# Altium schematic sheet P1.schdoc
size 297 x 209 mm; Symbol: Drawing-Symbol_A4; Company: 嘉立创EDA; Version: V1.0; Page Size: A4; @Project Name: STM32-glove; @Page Count: 1; @Update Date: 2025-11-29; @Create Date: 2025-11-28; @Schematic Name: Schematic1; @Page No: 1; @Page Name: P1; @Board Name: Board1; @Create Time: 15:31:41; @Update Time: 04:53:44; Border: 1; Title Block Position: 3; Size: A4; Width: 1170; Height: 825; Region Start: 1; X Region Count: 6; Y Region Count: 4; Blade Width: 10; Device: Drawing-Symbol_A4
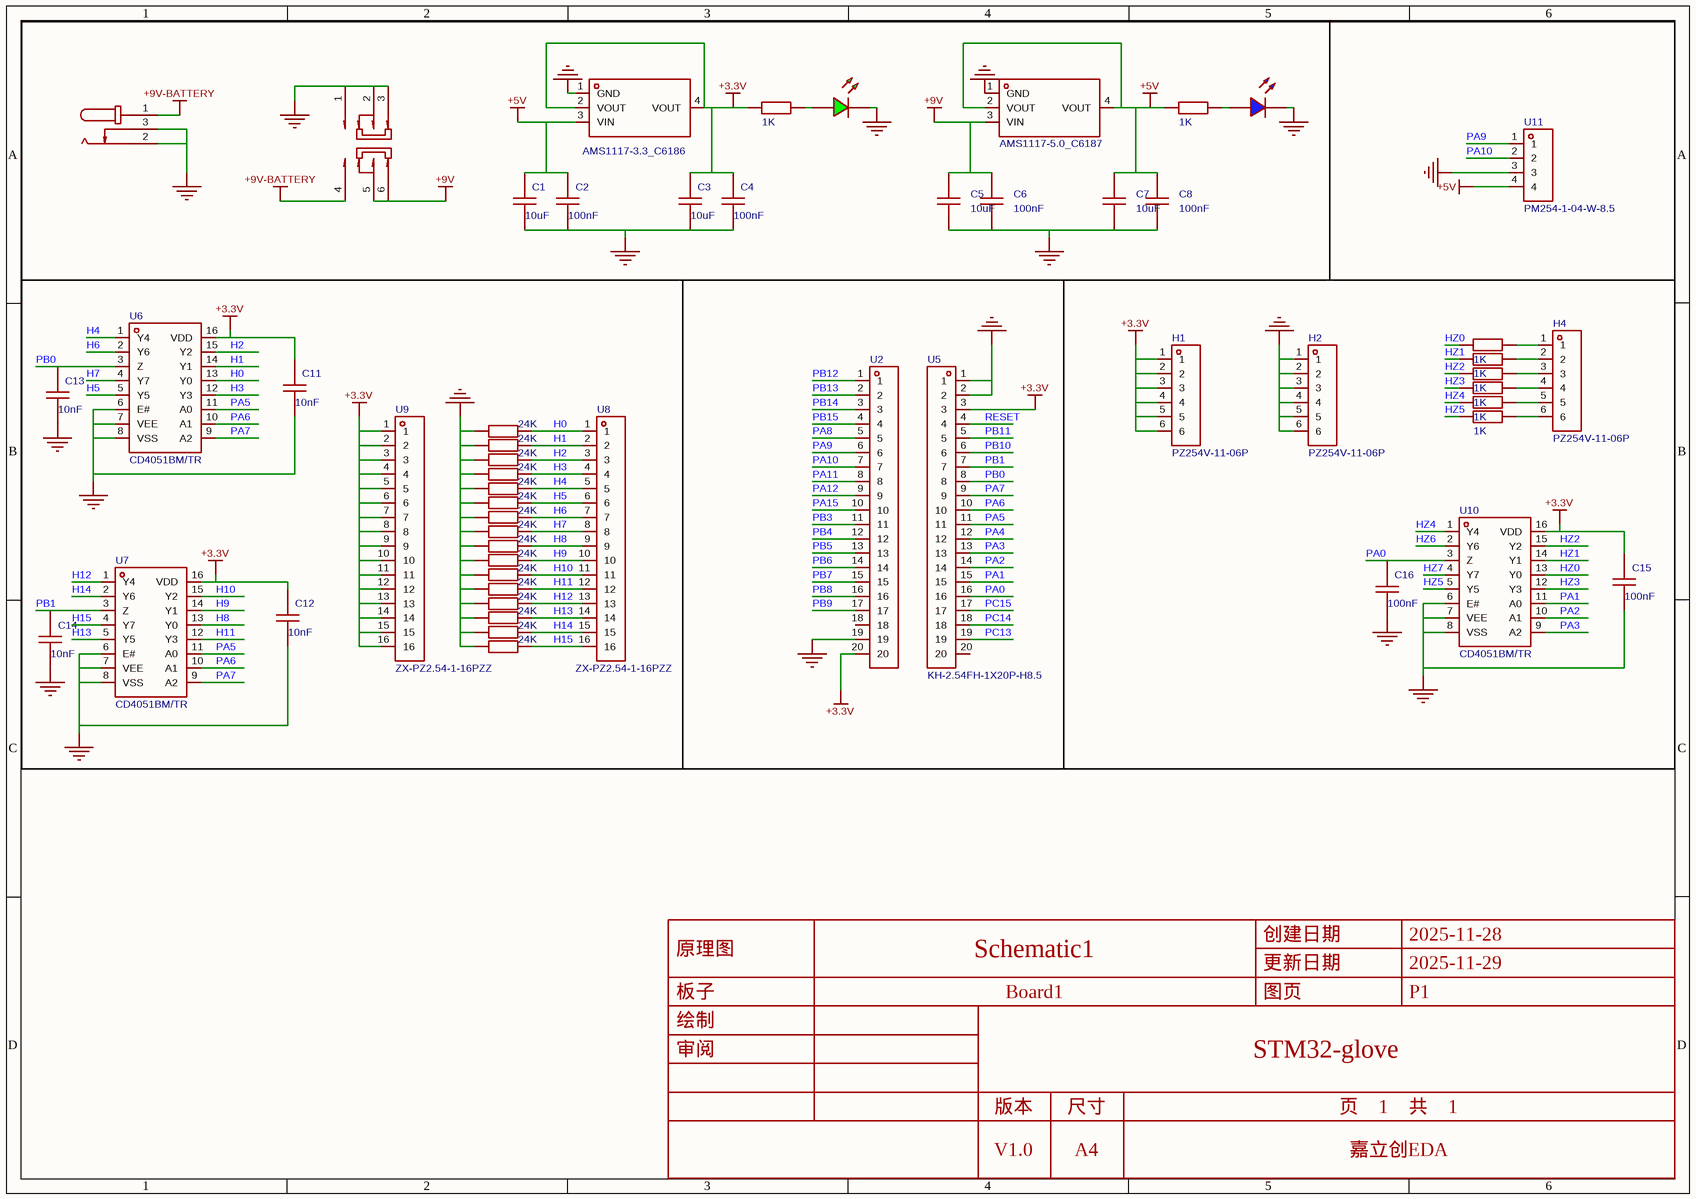
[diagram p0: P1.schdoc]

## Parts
C1  10uF  [C0805]
C2  100nF  [C0805]
C3  10uF  [C0805]
C4  100nF  [C0805]
C5  10uF  [C0805]
C6  100nF  [C0805]
C7  10uF  [C0805]
C8  100nF  [C0805]
C11  10nF  [C0805]
C12  10nF  [C0805]
C13  10nF  [C0805]
C14  10nF  [C0805]
C15  100nF  [C0805]
C16  100nF  [C0805]
DC1  DC-005-5A-2.0  [DC-IN-TH_DC-005-5A-2.0]  (value not drawn)
H1  PZ254V-11-06P  [HDR-TH_6P-P2.54-V-M]
H2  PZ254V-11-06P  [HDR-TH_6P-P2.54-V-M]
H4  PZ254V-11-06P  [HDR-TH_6P-P2.54-V-M]
LED1  LED_0805-G  [LED_0805]  (value not drawn)
LED2  LED_0805-B  [LED_0805]  (value not drawn)
R1  1K  [R0603]
R2  1K  [R0603]
R3  24K  [R0603]
R4  24K  [R0603]
R5  24K  [R0603]
R6  24K  [R0603]
R7  24K  [R0603]
R8  24K  [R0603]
R9  24K  [R0603]
R10  24K  [R0603]
R11  24K  [R0603]
R12  24K  [R0603]
R13  24K  [R0603]
R14  24K  [R0603]
R15  24K  [R0603]
R16  24K  [R0603]
R17  24K  [R0603]
R18  24K  [R0603]
R19  1K  [R0603]
R20  1K  [R0603]
R21  1K  [R0603]
R22  1K  [R0603]
R23  1K  [R0603]
R24  1K  [R0603]
SW1  SS-3235S-L1  [SW-SMD_SS-3235S-LX]  (value not drawn)
U2  KH-2.54FH-1X20P-H8.5  [HDR-TH_20P-P2.54-V-F-2]  (value not drawn)
U3  AMS1117-3.3_C6186  [SOT-223-3_L6.5-W3.4-P2.30-LS7.0-BR]
U4  AMS1117-5.0_C6187  [SOT-223_L6.5-W3.5-P2.30-LS7.0-BR]
U5  KH-2.54FH-1X20P-H8.5  [HDR-TH_20P-P2.54-V-F-2]
U6  CD4051BM/TR  [SOP-16_L9.9-W3.9-P1.27-LS6.1-BL]
U7  CD4051BM/TR  [SOP-16_L9.9-W3.9-P1.27-LS6.1-BL]
U8  ZX-PZ2.54-1-16PZZ  [HDR-TH_16P-P2.54-V-M-2]
U9  ZX-PZ2.54-1-16PZZ  [HDR-TH_16P-P2.54-V-M-2]
U10  CD4051BM/TR  [SOP-16_L9.9-W3.9-P1.27-LS6.1-BL]
U11  PM254-1-04-W-8.5  [HDR-TH_4P-P2.54-H-F-W10.0-N]

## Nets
+3.3V: C3.2 C4.2 C11.2 C12.2 C15.2 H1.1 H1.2 H1.3 H1.4 H1.5 H1.6 R1.1 U2.20 U3.2(VOUT) U3.4(VOUT) U5.3 U6.16(VDD) U7.16(VDD) U9.1 U9.2 U9.3 U9.4 U9.5 U9.6 U9.7 U9.8 U9.9 U9.10 U9.11 U9.12 U9.13 U9.14 U9.15 U9.16 U10.16(VDD)
+5V: C1.2 C2.2 C7.2 C8.2 R2.1 U3.3(VIN) U4.2(VOUT) U4.4(VOUT) U11.4
+9V: C5.2 C6.2 SW1.5 SW1.6 U4.3(VIN)
+9V-BATTERY: DC1.1 SW1.4
GND: C1.1 C2.1 C3.1 C4.1 C5.1 C6.1 C7.1 C8.1 C11.1 C12.1 C13.1 C14.1 C15.1 C16.1 DC1.2 DC1.3 H2.1 H2.2 H2.3 H2.4 H2.5 H2.6 LED1.1(C) LED2.1(C) R3.1 R4.1 R5.1 R6.1 R7.1 R8.1 R9.1 R10.1 R11.1 R12.1 R13.1 R14.1 R15.1 R16.1 R17.1 R18.1 SW1.1 SW1.2 SW1.3 U2.19 U3.1(GND) U4.1(GND) U5.1 U5.2 U6.6(E#) U6.7(VEE) U6.8(VSS) U7.6(E#) U7.7(VEE) U7.8(VSS) U10.6(E#) U10.7(VEE) U10.8(VSS) U11.3
H0: R3.2 U6.13(Y0) U8.1
H1: R4.2 U6.14(Y1) U8.2
H2: R5.2 U6.15(Y2) U8.3
H3: R6.2 U6.12(Y3) U8.4
H4: R7.2 U6.1(Y4) U8.5
H5: R8.2 U6.5(Y5) U8.6
H6: R9.2 U6.2(Y6) U8.7
H7: R10.2 U6.4(Y7) U8.8
H8: R11.2 U7.13(Y0) U8.9
H9: R12.2 U7.14(Y1) U8.10
H10: R13.2 U7.15(Y2) U8.11
H11: R14.2 U7.12(Y3) U8.12
H12: R15.2 U7.1(Y4) U8.13
H13: R16.2 U7.5(Y5) U8.14
H14: R17.2 U7.2(Y6) U8.15
H15: R18.2 U7.4(Y7) U8.16
HZ0: R19.1 U10.13(Y0)
HZ1: R20.1 U10.14(Y1)
HZ2: R21.1 U10.15(Y2)
HZ3: R22.1 U10.12(Y3)
HZ4: R23.1 U10.1(Y4)
HZ5: R24.1 U10.5(Y5)
HZ6: U10.2(Y6)
HZ7: U10.4(Y7)
PA0: C16.2 U5.16 U10.3(Z)
PA1: U5.15 U10.11(A0)
PA2: U5.14 U10.10(A1)
PA3: U5.13 U10.9(A2)
PA4: U5.12
PA5: U5.11 U6.11(A0) U7.11(A0)
PA6: U5.10 U6.10(A1) U7.10(A1)
PA7: U5.9 U6.9(A2) U7.9(A2)
PA8: U2.5
PA9: U2.6 U11.1
PA10: U2.7 U11.2
PA11: U2.8
PA12: U2.9
PA15: U2.10
PB0: C13.2 U5.8 U6.3(Z)
PB1: C14.2 U5.7 U7.3(Z)
PB3: U2.11
PB4: U2.12
PB5: U2.13
PB6: U2.14
PB7: U2.15
PB8: U2.16
PB9: U2.17
PB10: U5.6
PB11: U5.5
PB12: U2.1
PB13: U2.2
PB14: U2.3
PB15: U2.4
PC13: U5.19
PC14: U5.18
PC15: U5.17
RESET: U5.4
NetH4_1: H4.1 R19.2
NetH4_2: H4.2 R20.2
NetH4_3: H4.3 R21.2
NetH4_4: H4.4 R22.2
NetH4_5: H4.5 R23.2
NetH4_6: H4.6 R24.2
NetLED1_2: LED1.2(A) R1.2
NetLED2_2: LED2.2(A) R2.2

Not connected (* = marked no-connect by the designer): U2 18; U5 20

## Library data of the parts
C1-C8 C11 C12 = CAP_0805: Symbol: Capacitance; ConvertToPcb: yes; ModelId: 1ba041120af144c991958decab20d241; ModelName: C0805_L2.0-W1.3-H1.3; ModelTransform: 78.74,51.181,0,0,0,0,0,0.0005,0
C13-C16 = CAP_0805: Symbol: Capacitance; 3D Model: 1ba041120af144c991958decab20d241; 3D Model Transform: 78.74,51.181,0,0,0,0,0,0.0005,0; ConvertToPcb: yes; ModelName: C0805_L2.0-W1.3-H1.3
DC1 = DC-005-5A-2.0: 连接器类型:DC电源插座;安装方式:弯插;触点内径:2mm;触点外径:6.2mm;额定电流:5A;额定电压:24V;工作温度:-20℃~+70℃;; Manufacturer: XKB Connection(中国星坤); AddInBom: yes; ModelId: a22f313e2e2f40b7840423482609346e; ModelName: DC-IN-TH_L14.4-W9.0-H11.0; ModelTransform: 366.141,566.928,0,270,0,0,-143.701,86.614,-157.48; Connector Type: DC电源插座; Inside Contact Diameter: 2mm; Outside Contact Diameter: 6.2mm; Current Rating: 5A; Voltage Rating (Max): 24V
H1 H2 H4 = PZ254V-11-06P: 插针结构:1x6P;间距:2.54mm;行距:-;圆针/方针:方针;安装方式:直插;排数:单排;总PIN位数:6P;额定电流:-;额定电压:-;配合针长度:6mm;塑高:2.5mm;端接针长度:3mm;触头材质:黄铜;触头镀层:-;工作温度:-40℃~+105℃;颜色:黑色;; Manufacturer: XFCN(兴飞); AddInBom: yes; ModelId: 66a147c6933d4029b68665bbcd1e29240819f05c4eef4c71ace90d822a990e87; ModelName: HDR-TH_6P-P2.54-M-LI-1X6P; ModelTransform: 590.1563,98.425,0,0,0,0,0,0,-118.11; Pin Structure: 1x6P; Pitch: 2.54mm; Circluar Pins/Square Pins: 方针
LED1 = LED_0805-G: Symbol: LED_G; Convert to PCB: yes; 3D Model: 381ae4d721d6485eaad9d0ca067812b5; 3D Model Transform: 63.9,39.8,31.9,0,0,0,0,0,0; ModelName: LED-0805_G
LED2 = LED_0805-B: Symbol: LED_B; Convert to PCB: yes; 3D Model: 15b3689d29af4f66b19acfbf3642d2c8; 3D Model Transform: 79,49.2,39.4,0,0,0,0,0,0; ModelName: LED-0805_B
R1-R18 = Res_0603: Symbol: 电阻; ConvertToPcb: yes; ModelId: fc143cca1e79419f9cd78b61e9279f08; ModelTransform: 31.8897,63.7794,0,90,0,0,0,0,0
R19-R24 = Res_0603: Symbol: 电阻; 3D Model: fc143cca1e79419f9cd78b61e9279f08; 3D Model Transform: 31.8897,63.7794,0,90,0,0,0,0,0; ConvertToPcb: yes
SW1 = SS-3235S-L1: 电路结构:双刀双掷;安装方式:卧贴;开关颜色:黑色;额定电流:50mA;额定电压:12V;工作寿命:1万次;; Manufacturer: XKB Connection(中国星坤); AddInBom: yes; ModelId: e98810a9d4c646b4962907642f59f826; ModelTransform: 356.299,271.653,0,0,0,0,0.002,-0.004,0; Circuit: 双刀双掷; Actuator Style: 矩形柱状; Switch Height: 3.2mm; Actuator Color: 黑色; Current Rating: 50mA; Voltage Rating: 12V; Life: 1万次
U2 U5 = KH-2.54FH-1X20P-H8.5: 插孔结构:1x20P;间距:2.54mm;行距:-;圆孔/方孔:方孔;安装方式:直插;排数:单排;总孔位数:20P;额定电流:3A;额定电压:-;插孔方向:顶部;塑高:8.5mm;工作温度:-40℃~+105℃;; Manufacturer: kinghelm(金航标); AddInBom: yes; ModelId: 48d3332f1f604cb48783c9ca75931f3b0819f05c4eef4c71ace90d822a990e87; ModelTransform: 1999.996,98.8187,0,0,0,0,0,0,-106.299; Holes Structure: 1x20P; Pitch: 2.54mm; Circular Hole / Square Hole: 方孔; Number of Positions: 20P; Current Rating: 3A; Holes Direction: 顶部
U3 = AMS1117-3.3_C6186: 输出类型:固定;工作电压:16V;输出电压:3.3V;输出电流:1A;电源纹波抑制比(PSRR):72dB@(120Hz);输出极性:正极;; Manufacturer: AMS; AddInBom: yes; ModelId: 925194bf9823436183a3e0b978a8d076; ModelName: SOT-223-4P_L6.5-W3.5-H1.6-LS7.0-P2.30; ModelTransform: 279.89794,255.905,0,180,0,0,-3.9385,-0.0005,0; Output Type: 固定; Voltage - Supply: 16V; Output Voltage: 3.3V; Output Current: 1A; Voltage Dropout: 1.1V@(800mA); standby current: 5mA; Noise: 0.003%Vout; Output Configuration: 正极; Number of Outputs: 1
U4 = AMS1117-5.0_C6187: 输出类型:固定;工作电压:15V;输出电压:5V;输出电流:1A;电源纹波抑制比(PSRR):60dB;输出极性:正极;; Manufacturer: AMS; AddInBom: yes; ModelId: 925194bf9823436183a3e0b978a8d076; ModelName: SOT-223-4P_L6.5-W3.5-H1.6-LS7.0-P2.30; ModelTransform: 279.89794,255.905,0,180,0,0,0.0005,0.0005,0; Output Type: 固定; Voltage - Supply: 15V; Output Voltage: 5V; Output Current: 1A; Power Supply Rejection Ratio (PSRR): 60dB; Voltage Dropout: 1.3V; Output Configuration: 正极; Number of Outputs: 1
U6 U7 = CD4051BM/TR: 开关电路:单刀八掷(SP8T);通道数:8;导通电阻(Ron@VCC):60Ω;; Manufacturer: HGSEMI(华冠); AddInBom: yes; ModelId: abad049ca56d4fc098aa86460b5cb779; ModelTransform: 389.763,240.157,0,0,0,0,0,0,0; Number of Channels: 8; Supply Voltage: 3V~15V; On-State Resistance (Max): 60Ω
U8 U9 = ZX-PZ2.54-1-16PZZ: 插针结构:1x16P;间距:2.54mm;行距:-;圆针/方针:方针;安装方式:直插;排数:单排;总PIN位数:16P;额定电流:3A;额定电压:-;配合针长度:6mm;塑高:2.5mm;端接针长度:3mm;触头材质:黄铜;触头镀层:金;工作温度:-40℃~+105℃;颜色:黑色;; Manufacturer: Megastar(兆星); AddInBom: yes; ModelId: 9d8f5fca85624841a5ef0a3eef9dc35a0819f05c4eef4c71ace90d822a990e87; ModelTransform: 1592.16225,98.425,0,0,0,0,0,0,-118.11; Pin Structure: 1x16P; Pitch: 2.54mm; Circluar Pins/Square Pins: 方针; Current Rating: 3A
U10 = CD4051BM/TR: 开关电路:单刀八掷(SP8T);通道数:8;导通电阻(Ron@VCC):60Ω;; Manufacturer: HGSEMI(华冠); 3D Model: abad049ca56d4fc098aa86460b5cb779; 3D Model Transform: 389.763,240.157,0,0,0,0,0,0,0; Number of Channels: 8; Supply Voltage: 3V~15V; On-State Resistance (Max): 60Ω; AddInBom: yes
U11 = PM254-1-04-W-8.5: 插孔结构:1x4P;间距:2.54mm;行距:-;圆孔/方孔:方孔;安装方式:弯插;排数:单排;总孔位数:4P;额定电流:3A;额定电压:-;插孔方向:侧面;塑高:8.5mm;触头材质:铜合金;工作温度:-40℃~+105℃;; Manufacturer: HCTL(华灿天禄); AddInBom: yes; ModelId: f3aea7e76cee41099dd7459ba1f81f0c0819f05c4eef4c71ace90d822a990e87; ModelTransform: 415.7472,419.291,0,0,0,0,0,-196.85,-125.984; Holes Structure: 1x4P; Pitch: 2.54mm; Circular Hole / Square Hole: 方孔; Number of Positions: 4P; Current Rating: 3A; Holes Direction: 侧面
